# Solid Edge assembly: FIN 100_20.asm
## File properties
Title: Zylinder
Author: bmolnar
Template: iso assembly.asm
Last saved by: bmolnar
Revision: 7
Application: Solid Edge
Username: bmolnar
Dokumentum tartalom típus: 1
Document Number: FIN 100/20
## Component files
Kolbenstange.par
Profilrohr.par
Kit_1.par
Kit_2.par
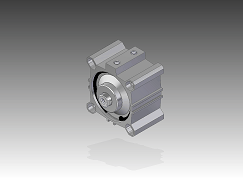
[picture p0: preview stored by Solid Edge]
